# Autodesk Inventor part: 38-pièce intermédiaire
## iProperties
Created: 2011-02
Part Number: 38-pièce intermédiaire
Document SubType Name: Modeling
Designer: eric
Density: 1 g/cm^3
Author: eric
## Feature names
1. Base1
